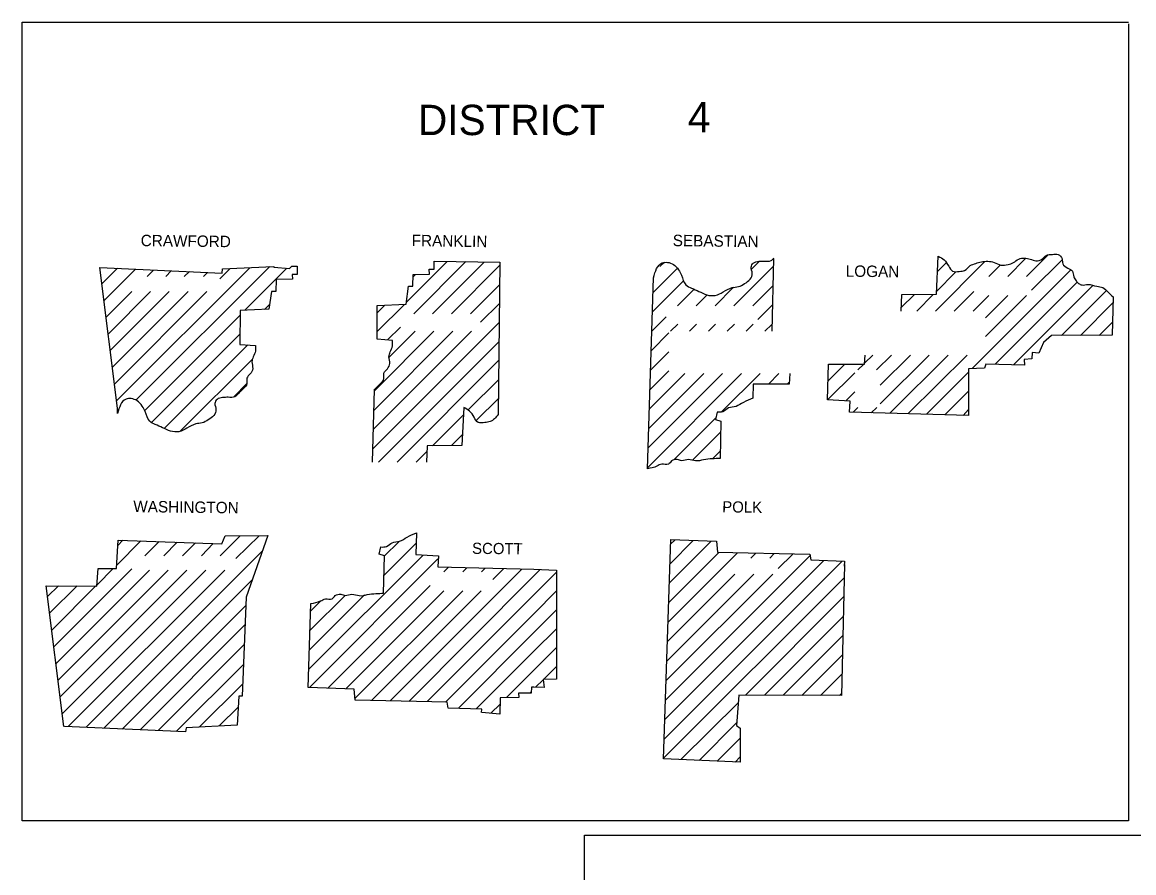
# Model space of a CAD drawing. Extents: x 23481 to 28196, y 1325020 to 1327623.
# Drawn here: x 27376.6 to 27794.3, y 1326493.4 to 1326812.9 of the extents above; entities that cross this region are included whole.
import ezdxf

# ---------------------------------------------------------------- set-up
doc = ezdxf.new("R2010")
doc.units = 0
doc.layers.add('S_ELECTRIC_UTILITIES_ANNOT', color=7, linetype='Continuous')

msp = doc.modelspace()

# ---------------------------------------------------------------- linework, layer by layer
at = {"layer": 'S_ELECTRIC_UTILITIES_ANNOT'}
msp.add_line((27792.32, 1326812.26), (27792.32, 1326512.86), dxfattribs=at)
for points in [[(27376.62, 1326512.86), (27376.62, 1326812.86), (27792.32, 1326812.86)], [(27658.92, 1326724.16), (27658.22, 1326696.76)], [(27706.82, 1326704.36), (27707.12, 1326710.56), (27720.12, 1326710.66), (27720.82, 1326724.96)], [(27746.92, 1326717.36), (27753.62, 1326724.06)], [(27754.02, 1326717.36), (27762.02, 1326725.36)], [(27405.82, 1326720.76), (27451.72, 1326718.66), (27451.92, 1326720.26), (27470.92, 1326721.16)], [(27412.42, 1326665.86), (27412.42, 1326667.86), (27405.82, 1326720.76)], [(27406.62, 1326714.66), (27412.42, 1326720.46)], [(27407.42, 1326708.36), (27419.12, 1326720.16)], [(27412.12, 1326670.76), (27462.12, 1326720.66)], [(27419.42, 1326670.96), (27469.62, 1326721.06)], [(27423.52, 1326717.36), (27425.92, 1326719.76)], [(27450.82, 1326716.46), (27454.62, 1326720.26)], [(27479.92, 1326721.26), (27479.92, 1326718.16), (27478.02, 1326718.16), (27478.12, 1326716.36), (27472.02, 1326716.26), (27471.92, 1326711.76), (27470.22, 1326711.76), (27469.32, 1326705.06), (27458.52, 1326704.56), (27458.42, 1326691.86), (27464.22, 1326691.46)], [(27460.22, 1326704.66), (27476.02, 1326720.46)], [(27471.12, 1326721.16), (27471.12, 1326720.86), (27477.02, 1326720.36), (27477.92, 1326721.26), (27479.92, 1326721.26)], [(27515.72, 1326693.36), (27509.92, 1326693.76), (27510.02, 1326706.46), (27520.82, 1326706.96), (27521.72, 1326713.66), (27523.42, 1326713.66), (27523.52, 1326718.16), (27529.62, 1326718.26), (27529.52, 1326720.06), (27531.42, 1326720.06), (27531.42, 1326723.16)], [(27520.92, 1326707.56), (27536.32, 1326722.96)], [(27523.72, 1326703.36), (27543.32, 1326722.96)], [(27530.82, 1326703.36), (27550.22, 1326722.76)], [(27531.42, 1326723.16), (27556.12, 1326722.76)], [(27537.92, 1326703.36), (27556.02, 1326721.56)], [(27556.12, 1326722.76), (27555.42, 1326665.46)], [(27613.52, 1326711.26), (27622.72, 1326720.36)], [(27616.22, 1326721.06), (27617.92, 1326722.76)], [(27644.02, 1326706.36), (27658.82, 1326721.16)], [(27650.62, 1326720.06), (27653.62, 1326723.06)], [(27719.72, 1326704.36), (27738.32, 1326722.96)], [(27720.52, 1326719.26), (27723.72, 1326722.46)], [(27733.52, 1326682.76), (27770.52, 1326719.76)], [(27739.82, 1326717.36), (27744.12, 1326721.66)], [(27755.82, 1326712.16), (27767.32, 1326723.56)], [(27430.52, 1326717.36), (27432.62, 1326719.46)], [(27437.52, 1326717.36), (27439.42, 1326719.26)], [(27444.72, 1326717.36), (27446.22, 1326718.86)], [(27523.42, 1326717.16), (27524.42, 1326718.16)], [(27611.52, 1326645.16), (27613.82, 1326716.86)], [(27613.42, 1326704.06), (27625.12, 1326715.76)], [(27720.12, 1326711.76), (27727.32, 1326718.96)], [(27408.22, 1326702.16), (27417.82, 1326711.66)], [(27409.02, 1326695.86), (27424.82, 1326711.66)], [(27409.72, 1326689.56), (27431.82, 1326711.66)], [(27410.52, 1326683.26), (27439.02, 1326711.66)], [(27411.32, 1326676.96), (27446.02, 1326711.66)], [(27545.02, 1326703.36), (27556.02, 1326714.36)], [(27622.82, 1326706.36), (27628.92, 1326712.46)], [(27636.92, 1326706.36), (27643.92, 1326713.36)], [(27651.12, 1326706.36), (27658.62, 1326713.86)], [(27726.82, 1326704.36), (27734.12, 1326711.66)], [(27742.22, 1326684.36), (27773.02, 1326715.16)], [(27749.02, 1326684.16), (27778.92, 1326713.96)], [(27767.12, 1326695.16), (27784.02, 1326712.06)], [(27548.82, 1326700.16), (27555.92, 1326707.26)], [(27629.82, 1326706.36), (27633.82, 1326710.36)], [(27706.92, 1326705.66), (27711.82, 1326710.56)], [(27712.72, 1326704.36), (27718.92, 1326710.56)], [(27786.52, 1326709.66), (27786.12, 1326695.26), (27763.32, 1326695.16), (27760.32, 1326692.56), (27758.62, 1326688.56), (27756.12, 1326688.76), (27756.02, 1326686.46), (27753.12, 1326686.16), (27753.22, 1326684.06), (27738.72, 1326684.46), (27738.22, 1326682.86), (27732.22, 1326682.66), (27732.12, 1326665.16)], [(27733.92, 1326704.36), (27739.82, 1326710.26)], [(27738.52, 1326694.86), (27754.02, 1326710.26)], [(27738.52, 1326701.86), (27746.92, 1326710.26)], [(27774.22, 1326695.16), (27786.42, 1326707.46)], [(27422.72, 1326667.06), (27458.52, 1326702.86)], [(27467.62, 1326704.96), (27469.52, 1326706.86)], [(27509.92, 1326696.66), (27520.22, 1326706.86)], [(27509.92, 1326703.66), (27512.82, 1326706.56)], [(27653.02, 1326701.16), (27658.42, 1326706.56)], [(27508.32, 1326652.56), (27555.82, 1326700.06)], [(27613.22, 1326696.76), (27618.62, 1326702.16)], [(27620.22, 1326696.76), (27622.92, 1326699.46)], [(27627.32, 1326696.76), (27630.02, 1326699.46)], [(27634.42, 1326696.76), (27637.12, 1326699.46)], [(27641.52, 1326696.76), (27644.22, 1326699.46)], [(27648.62, 1326696.76), (27651.32, 1326699.46)], [(27655.62, 1326696.76), (27658.22, 1326699.36)], [(27781.32, 1326695.16), (27786.22, 1326700.16)], [(27425.22, 1326662.56), (27458.52, 1326695.86)], [(27508.52, 1326659.86), (27545.42, 1326696.76)], [(27508.72, 1326667.06), (27538.42, 1326696.76)], [(27508.92, 1326674.36), (27531.32, 1326696.76)], [(27513.92, 1326693.56), (27518.72, 1326698.36)], [(27514.52, 1326687.06), (27524.22, 1326696.76)], [(27612.92, 1326689.46), (27619.62, 1326696.16)], [(27430.02, 1326660.36), (27461.42, 1326691.66)], [(27510.52, 1326647.66), (27555.72, 1326692.86)], [(27436.02, 1326659.26), (27463.12, 1326686.26)], [(27612.72, 1326682.16), (27619.62, 1326689.06)], [(27732.12, 1326665.16), (27687.42, 1326666.36), (27687.72, 1326670.46), (27679.22, 1326670.96), (27679.62, 1326684.36), (27693.12, 1326684.46), (27693.32, 1326687.86)], [(27693.22, 1326684.86), (27696.22, 1326687.86)], [(27697.62, 1326682.26), (27703.22, 1326687.86)], [(27699.02, 1326669.56), (27717.42, 1326687.86)], [(27699.02, 1326676.56), (27710.32, 1326687.86)], [(27702.62, 1326665.96), (27724.52, 1326687.86)], [(27709.42, 1326665.76), (27731.62, 1326687.86)], [(27517.52, 1326647.66), (27555.62, 1326685.76)], [(27612.52, 1326674.86), (27619.62, 1326681.96)], [(27679.52, 1326678.26), (27685.72, 1326684.46)], [(27690.62, 1326682.26), (27692.82, 1326684.46)], [(27544.32, 1326667.36), (27555.52, 1326678.56)], [(27611.62, 1326645.66), (27646.82, 1326680.86)], [(27611.82, 1326652.96), (27639.72, 1326680.86)], [(27612.02, 1326660.26), (27632.72, 1326680.86)], [(27612.22, 1326667.46), (27625.62, 1326680.86)], [(27639.42, 1326666.46), (27653.92, 1326680.86)], [(27665.02, 1326680.86), (27664.82, 1326676.96), (27651.32, 1326676.86), (27651.12, 1326671.66)], [(27657.02, 1326676.96), (27660.92, 1326680.86)], [(27679.22, 1326670.96), (27689.42, 1326681.16)], [(27716.42, 1326665.66), (27732.32, 1326681.56)], [(27456.12, 1326672.16), (27461.02, 1326677.16)], [(27508.22, 1326647.66), (27508.92, 1326674.96)], [(27664.02, 1326676.96), (27664.82, 1326677.66)], [(27686.02, 1326670.66), (27689.42, 1326674.06)], [(27723.22, 1326665.36), (27732.32, 1326674.46)], [(27547.32, 1326663.36), (27555.52, 1326671.46)], [(27542.52, 1326668.16), (27541.82, 1326653.86), (27528.82, 1326653.76), (27528.52, 1326647.66)], [(27530.72, 1326653.76), (27542.52, 1326665.56)], [(27637.72, 1326666.36), (27637.12, 1326663.66), (27639.12, 1326663.06), (27638.82, 1326648.96)], [(27688.82, 1326666.36), (27690.62, 1326668.16)], [(27695.62, 1326666.16), (27697.72, 1326668.16)], [(27730.12, 1326665.16), (27732.22, 1326667.36)], [(27621.42, 1326648.46), (27637.22, 1326664.26)], [(27537.92, 1326653.86), (27542.02, 1326658.06)], [(27628.42, 1326648.36), (27639.12, 1326659.06)], [(27524.62, 1326647.66), (27528.72, 1326651.76)], [(27636.12, 1326648.96), (27638.92, 1326651.76)], [(27385.92, 1326601.16), (27404.62, 1326601.06), (27405.12, 1326607.66), (27412.02, 1326607.66), (27412.62, 1326618.36), (27451.62, 1326616.96), (27452.82, 1326619.96), (27468.92, 1326620.06), (27460.82, 1326596.86), (27459.22, 1326559.76), (27458.02, 1326559.66), (27457.42, 1326548.76)], [(27451.02, 1326612.46), (27458.52, 1326619.96)], [(27456.92, 1326611.36), (27465.62, 1326619.96)], [(27524.72, 1326621.06), (27524.52, 1326612.86), (27533.02, 1326612.36), (27532.72, 1326608.26), (27568.82, 1326607.36)], [(27412.12, 1326608.96), (27421.12, 1326618.06)], [(27412.52, 1326616.36), (27414.42, 1326618.26)], [(27422.72, 1326612.46), (27428.02, 1326617.76)], [(27429.82, 1326612.46), (27434.82, 1326617.56)], [(27436.82, 1326612.46), (27441.72, 1326617.36)], [(27443.92, 1326612.46), (27448.42, 1326617.06)], [(27512.42, 1326598.36), (27512.72, 1326612.46), (27510.72, 1326613.06), (27511.32, 1326615.76)], [(27512.62, 1326612.26), (27518.22, 1326617.86)], [(27512.62, 1326605.16), (27524.62, 1326617.16)], [(27617.52, 1326536.16), (27620.32, 1326618.56)], [(27619.82, 1326602.26), (27635.52, 1326617.96)], [(27620.02, 1326609.46), (27628.72, 1326618.16)], [(27620.22, 1326618.56), (27637.52, 1326617.96), (27637.92, 1326613.76), (27672.52, 1326613.06), (27672.92, 1326610.86), (27685.52, 1326610.46), (27685.42, 1326608.56)], [(27620.22, 1326616.76), (27621.92, 1326618.46)], [(27400.62, 1326548.06), (27466.82, 1326614.16)], [(27484.22, 1326569.76), (27527.22, 1326612.66)], [(27484.52, 1326562.96), (27532.82, 1326611.26)], [(27618.32, 1326558.26), (27672.62, 1326612.56)], [(27619.32, 1326587.46), (27645.32, 1326613.56)], [(27619.52, 1326594.86), (27638.32, 1326613.66)], [(27650.42, 1326611.56), (27652.22, 1326613.36)], [(27657.52, 1326611.56), (27659.12, 1326613.26)], [(27660.62, 1326607.66), (27666.12, 1326613.06)], [(27388.52, 1326578.26), (27417.82, 1326607.56)], [(27389.32, 1326571.96), (27424.42, 1326607.06)], [(27390.12, 1326565.76), (27431.42, 1326607.06)], [(27390.92, 1326559.46), (27438.52, 1326607.06)], [(27391.72, 1326553.16), (27445.62, 1326607.06)], [(27393.92, 1326548.36), (27452.72, 1326607.06)], [(27404.72, 1326601.56), (27410.82, 1326607.66)], [(27514.92, 1326557.96), (27564.32, 1326607.36)], [(27535.02, 1326606.36), (27536.82, 1326608.16)], [(27542.12, 1326606.36), (27543.62, 1326607.96)], [(27549.22, 1326606.36), (27550.62, 1326607.76)], [(27553.42, 1326603.56), (27557.42, 1326607.56)], [(27568.82, 1326607.36), (27577.42, 1326607.06)], [(27568.82, 1326604.86), (27571.22, 1326607.26)], [(27577.42, 1326607.06), (27577.32, 1326566.06), (27572.32, 1326565.96), (27572.72, 1326562.96), (27568.82, 1326563.06)], [(27685.52, 1326609.16), (27684.42, 1326559.96), (27645.92, 1326560.06), (27645.02, 1326548.66), (27646.42, 1326547.66), (27646.32, 1326534.86), (27617.52, 1326536.16)], [(27617.82, 1326543.56), (27684.72, 1326610.46)], [(27618.12, 1326550.96), (27677.82, 1326610.66)], [(27407.42, 1326547.76), (27463.02, 1326603.36)], [(27521.82, 1326557.76), (27568.82, 1326604.86)], [(27568.82, 1326597.76), (27577.42, 1326606.26)], [(27617.62, 1326536.36), (27685.42, 1326604.16)], [(27618.52, 1326565.56), (27658.62, 1326605.56)], [(27618.82, 1326572.86), (27651.52, 1326605.56)], [(27619.02, 1326580.26), (27644.42, 1326605.56)], [(27392.22, 1326548.36), (27385.62, 1326601.16)], [(27386.12, 1326597.16), (27390.22, 1326601.16)], [(27386.92, 1326590.86), (27397.22, 1326601.16)], [(27387.72, 1326584.56), (27404.22, 1326601.16)], [(27491.42, 1326562.76), (27529.92, 1326601.26)], [(27498.22, 1326562.46), (27535.02, 1326599.26)], [(27501.72, 1326558.96), (27542.12, 1326599.26)], [(27508.02, 1326558.16), (27549.12, 1326599.26)], [(27568.82, 1326590.66), (27577.42, 1326599.26)], [(27484.02, 1326562.96), (27485.12, 1326594.56)], [(27484.52, 1326577.06), (27505.22, 1326597.76)], [(27484.82, 1326584.46), (27498.02, 1326597.56)], [(27485.12, 1326591.76), (27488.72, 1326595.36)], [(27528.72, 1326557.66), (27568.82, 1326597.76)], [(27648.42, 1326560.06), (27685.22, 1326596.96)], [(27414.12, 1326547.36), (27460.72, 1326593.86)], [(27535.62, 1326557.46), (27568.82, 1326590.66)], [(27568.82, 1326583.56), (27577.42, 1326592.16)], [(27420.92, 1326547.06), (27460.32, 1326586.46)], [(27655.52, 1326560.06), (27685.02, 1326589.66)], [(27540.52, 1326555.26), (27568.82, 1326583.56)], [(27568.82, 1326576.56), (27577.32, 1326584.96)], [(27662.52, 1326560.06), (27684.92, 1326582.46)], [(27427.72, 1326546.76), (27460.02, 1326579.16)], [(27568.82, 1326569.46), (27577.32, 1326577.96)], [(27547.22, 1326554.96), (27568.82, 1326576.56)], [(27669.52, 1326559.96), (27684.72, 1326575.16)], [(27434.42, 1326546.46), (27459.72, 1326571.66)], [(27558.62, 1326559.16), (27568.82, 1326569.46)], [(27572.42, 1326565.96), (27577.32, 1326570.86)], [(27569.42, 1326563.06), (27572.32, 1326565.86)], [(27676.62, 1326559.96), (27684.52, 1326567.96)], [(27443.12, 1326548.06), (27459.32, 1326564.26)], [(27549.22, 1326553.56), (27549.32, 1326554.86), (27536.72, 1326555.26), (27536.32, 1326557.46), (27501.72, 1326558.16), (27501.32, 1326562.36), (27484.02, 1326562.96)], [(27568.82, 1326563.06), (27567.92, 1326563.06), (27567.82, 1326560.86), (27563.12, 1326560.86), (27563.22, 1326559.26), (27556.22, 1326559.06), (27556.12, 1326552.96), (27549.32, 1326553.56)], [(27567.32, 1326560.86), (27567.82, 1326561.36)], [(27552.72, 1326553.36), (27556.22, 1326556.76)], [(27624.12, 1326535.86), (27645.72, 1326557.36)], [(27683.72, 1326559.96), (27684.42, 1326560.66)], [(27450.62, 1326548.56), (27457.82, 1326555.66)], [(27457.42, 1326548.76), (27438.22, 1326547.86), (27438.02, 1326546.26), (27392.52, 1326548.36)], [(27630.92, 1326535.56), (27645.12, 1326549.76)], [(27637.72, 1326535.26), (27646.42, 1326543.96)], [(27644.52, 1326534.96), (27646.42, 1326536.86)], [(27792.32, 1326512.86), (27376.62, 1326512.86)]]:
    msp.add_lwpolyline(points, dxfattribs=at)
msp.add_lwpolyline([(27587.92, 1326207.46), (27587.92, 1326507.46), (27987.92, 1326507.46), (27987.92, 1326207.46)], close=True, dxfattribs=at)
for points in [[(27613.82, 1326716.86), (27617.12, 1326722.46), (27619.02, 1326722.66), (27621.32, 1326721.86), (27623.22, 1326719.86), (27624.32, 1326717.86), (27626.02, 1326714.16), (27628.12, 1326712.96), (27630.82, 1326711.76), (27633.82, 1326710.46), (27637.02, 1326710.26), (27640.02, 1326711.56), (27643.32, 1326713.16), (27645.72, 1326713.56), (27648.02, 1326714.66), (27650.12, 1326716.36), (27650.92, 1326718.56), (27650.52, 1326720.86), (27651.32, 1326722.36), (27653.42, 1326723.06), (27655.52, 1326723.16), (27658.02, 1326723.36), (27659.02, 1326724.26)], [(27720.82, 1326724.96), (27723.02, 1326723.56), (27724.72, 1326721.26), (27726.22, 1326719.36), (27728.72, 1326719.26), (27730.72, 1326719.66), (27732.82, 1326721.46)], [(27732.82, 1326721.46), (27737.02, 1326722.86), (27739.42, 1326723.06), (27741.82, 1326722.66), (27744.32, 1326721.66), (27747.02, 1326721.86), (27749.02, 1326722.56), (27751.02, 1326723.86), (27753.22, 1326724.26), (27755.32, 1326723.86), (27757.52, 1326723.26), (27759.92, 1326723.96), (27761.32, 1326725.26), (27763.72, 1326725.66), (27765.82, 1326725.66), (27767.32, 1326723.96), (27767.62, 1326722.16), (27769.52, 1326720.46), (27771.22, 1326719.36), (27771.72, 1326717.26), (27772.62, 1326715.76), (27773.52, 1326714.76), (27774.82, 1326714.16), (27777.02, 1326714.36), (27780.42, 1326713.66), (27782.62, 1326713.16), (27784.62, 1326711.46), (27786.52, 1326709.66)], [(27464.22, 1326691.46), (27464.22, 1326689.36), (27463.42, 1326687.16), (27462.92, 1326685.26), (27463.22, 1326682.76), (27462.32, 1326680.76), (27461.02, 1326679.16), (27461.02, 1326677.16), (27459.52, 1326675.06), (27457.92, 1326673.46), (27456.52, 1326672.16), (27454.02, 1326671.96), (27451.92, 1326671.86), (27449.82, 1326671.16), (27449.02, 1326669.66), (27449.42, 1326667.36), (27448.62, 1326665.16), (27446.52, 1326663.46), (27444.22, 1326662.36), (27441.82, 1326661.96), (27438.52, 1326660.36), (27435.52, 1326659.06), (27432.32, 1326659.26), (27429.32, 1326660.56), (27426.62, 1326661.76), (27424.52, 1326662.96), (27422.82, 1326666.66), (27421.72, 1326668.66), (27419.82, 1326670.66), (27417.52, 1326671.46), (27415.62, 1326671.26), (27412.42, 1326665.86)], [(27508.72, 1326674.76), (27509.42, 1326675.36), (27511.02, 1326676.96), (27512.52, 1326679.06), (27512.52, 1326681.06), (27513.82, 1326682.66), (27514.72, 1326684.66), (27514.42, 1326687.16), (27514.92, 1326689.06), (27515.72, 1326691.26), (27515.72, 1326693.36)], [(27651.12, 1326671.66), (27647.62, 1326670.06), (27644.82, 1326668.56), (27642.02, 1326667.96), (27639.92, 1326666.56), (27637.72, 1326666.36)], [(27555.42, 1326665.46), (27552.42, 1326662.86), (27550.42, 1326662.46), (27547.92, 1326662.56), (27546.42, 1326664.46), (27544.72, 1326666.76), (27542.52, 1326668.16)], [(27638.82, 1326648.96), (27635.92, 1326648.86), (27632.62, 1326648.46), (27629.62, 1326648.06), (27626.92, 1326648.56), (27624.42, 1326648.16), (27622.72, 1326648.56), (27620.62, 1326648.06), (27619.42, 1326646.86), (27616.92, 1326646.86), (27615.12, 1326646.06), (27611.52, 1326645.16)], [(27511.32, 1326615.76), (27513.52, 1326615.96), (27515.62, 1326617.36), (27518.42, 1326617.96), (27521.22, 1326619.46), (27524.72, 1326621.06)], [(27485.12, 1326594.56), (27488.72, 1326595.46), (27490.52, 1326596.26), (27493.02, 1326596.26), (27494.22, 1326597.46), (27496.32, 1326597.96), (27498.02, 1326597.56), (27500.52, 1326597.96), (27503.22, 1326597.46), (27506.22, 1326597.86), (27509.52, 1326598.26), (27512.42, 1326598.36)]]:
    msp.add_spline(points, degree=3, dxfattribs=at)

# ---------------------------------------------------------------- texts
for s, p in [('4', (27626.72, 1326771.56)), ('DISTRICT', (27525.32, 1326770.46))]:
    msp.add_text(s, height=11.4, dxfattribs=at).set_placement(p)
for s, height, rotation, p in [('CRAWFORD', 4.3, 359.2771, (27421.12, 1326728.76)), ('FRANKLIN', 4.301, 359.1815, (27522.92, 1326728.76)), ('SEBASTIAN', 4.3, 359.2816, (27621.02, 1326728.76)), ('LOGAN', 4.301, 359.3969, (27686.02, 1326717.26)), ('WASHINGTON', 4.3, 359.232, (27418.32, 1326628.86)), ('POLK', 4.199, 359.2152, (27639.62, 1326628.76)), ('SCOTT', 4.201, 359.4063, (27545.62, 1326613.16))]:
    msp.add_text(s, height=height, rotation=rotation, dxfattribs=at).set_placement(p)

doc.saveas('drawing.dxf')
